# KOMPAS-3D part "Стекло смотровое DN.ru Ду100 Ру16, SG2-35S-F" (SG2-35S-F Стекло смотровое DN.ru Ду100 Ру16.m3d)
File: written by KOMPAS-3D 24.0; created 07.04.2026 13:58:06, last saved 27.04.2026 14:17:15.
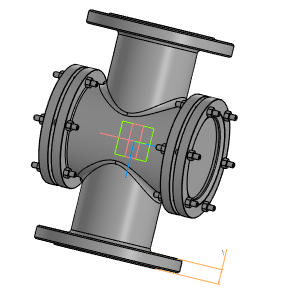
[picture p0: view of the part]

Document properties: Автор: Main; Полное имя файла: D:\DN.ru Аутсорс\Стекло смотровое DN.ru\SG2-35S-F Стекло смотровое DN.ru Ду100 Ру16\SG2-35S-F Стекло смотровое DN.ru Ду100 Ру16.m3d

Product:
- Body: Тело 1  | qty 1
    Масса: 25.876303
- Part/product: Стекло смотровое DN.ru Ду100 Ру16  | designation SG2-35S-F
    Масса: 26
    Раздел спецификации: Прочие изделия
    Примечание: D500-00099

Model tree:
1. Операция без истории:1
2. Линейный размер:1  (with: Грань.Операция без истории:1)
     Значение = 22

Expressions: SG2-35S-F
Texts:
  Точка начала. Х
  Точка начала. Y
  Точка начала. Z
